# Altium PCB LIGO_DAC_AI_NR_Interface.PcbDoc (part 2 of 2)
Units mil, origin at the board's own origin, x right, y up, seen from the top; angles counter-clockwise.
Board outline 2600 x 10000 mil, 4 copper layers (Top Layer, Mid-Layer 1, Mid-Layer 2, Bottom Layer), stack 61.8 mil thick; 21 components, 77 nets, 221 pads, 42 vias.
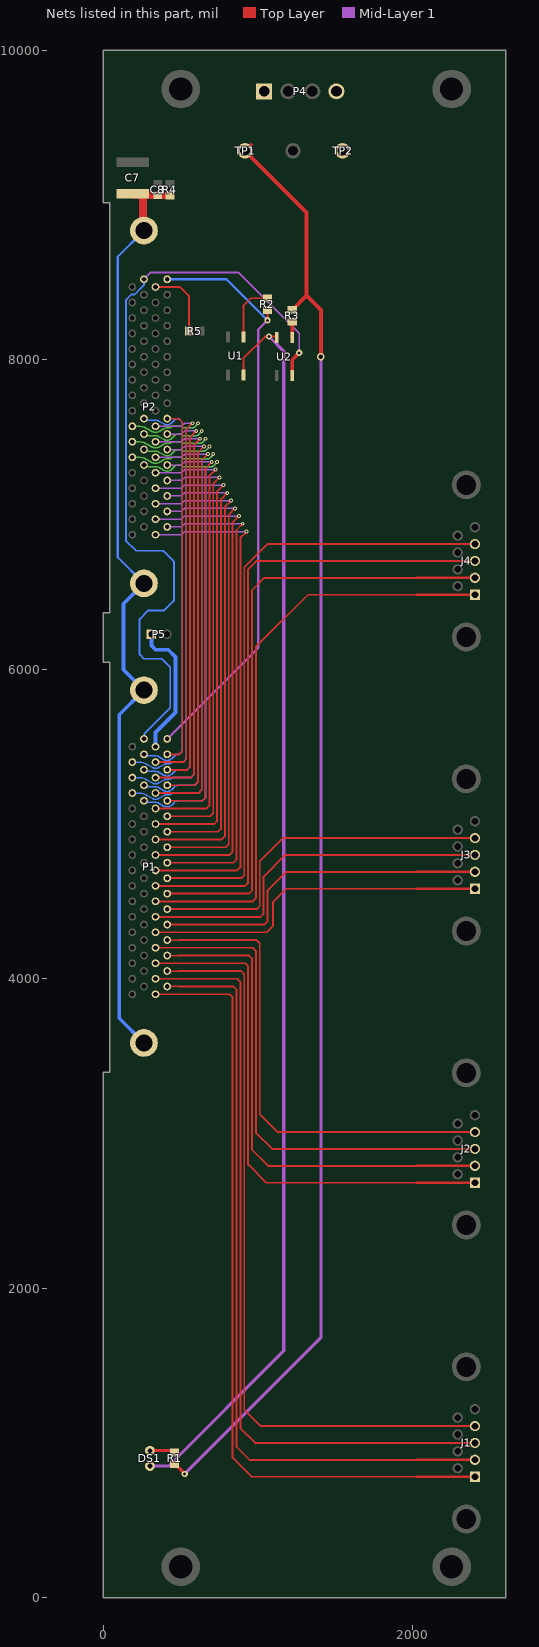
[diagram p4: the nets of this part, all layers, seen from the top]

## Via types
v1: diameter 25, hole 12, Top Layer to Bottom Layer, 30 vias
v2: diameter 40, hole 20, Top Layer to Bottom Layer, 11 vias
v3: diameter 50, hole 28, Top Layer to Bottom Layer, 1 vias

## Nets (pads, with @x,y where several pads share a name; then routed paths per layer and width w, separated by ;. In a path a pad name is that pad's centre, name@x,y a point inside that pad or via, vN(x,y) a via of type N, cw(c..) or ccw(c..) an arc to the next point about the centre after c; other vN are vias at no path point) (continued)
InputN26: P1.60 P2.44 | length 3166.4
  Mid-Layer 2 w8: v1@735,7337.52 v1(735,7340)
  Mid-Layer 2 w9: P2.44@261.81,7320 ccw(c285.95,7344.14) 285.95,7310 336.81,7310 cw(c336.81,7270) 358.01,7303.92 390.61,7286.08 ccw(c411.81,7320) 411.81,7280 ccw(c411.81,7320) 440.1,7291.72 440.1,7291.92 456.46,7308.28 cw(c484.74,7280) 484.74,7320 486.81,7320 505,7320
  Mid-Layer 2 w10: 505,7320 515,7310 702.28,7310 ccw(c702.28,7320) 707.64,7311.55 710.28,7313.23 716.74,7318.19 ccw(c700,7340) 723.39,7325.54 cw(c731.89,7320.27) 724.79,7327.31 733.25,7335.77 ccw(c729.02,7340) v1(735,7340)
  Bottom Layer w8: v1@735,7337.52 v1(735,7340)
  Bottom Layer w9: P1.60@261.81,5150 ccw(c285.95,5174.14) 285.95,5140 336.81,5140 cw(c336.81,5100) 358.01,5133.92 390.61,5116.08 ccw(c411.81,5150) 411.81,5110 ccw(c411.81,5150) 440.1,5121.72 440.1,5121.92 456.46,5138.28 cw(c484.74,5110) 484.74,5150
  Bottom Layer w10: 670,7310 702.28,7310 ccw(c702.28,7320) 707.64,7311.55 710.28,7313.23 716.74,7318.19 ccw(c700,7340) 723.39,7325.54 cw(c731.89,7320.27) 724.79,7327.31 733.25,7335.77 ccw(c729.02,7340) v1(735,7340)
  Bottom Layer w12: 484.74,5150 640,5150 660,5170 660,7296.81 ; 660,7300 670,7310
InputN27: P1.61 P2.45 | length 3257.4
  Mid-Layer 2 w8: v1@710,7387.52 v1(710,7390)
  Mid-Layer 2 w9: P2.45@186.81,7370 224.74,7370 226.94,7370 cw(c226.94,7264.19) 283.01,7353.92 283.21,7353.81 315.61,7336.08 ccw(c336.81,7370) 336.81,7330 ccw(c336.81,7370) 358.01,7336.08 390.61,7353.92 cw(c411.81,7320) 411.81,7360 424.74,7360 ccw(c424.74,7377.07) 436.81,7365 cw(c448.88,7352.93) 448.88,7370 486.81,7370 505,7370
  Mid-Layer 2 w10: 505,7370 515,7360 677.28,7360 ccw(c677.28,7370) 682.64,7361.55 685.28,7363.23 691.74,7368.19 ccw(c675,7390) 698.39,7375.54 cw(c706.89,7370.27) 699.79,7377.31 708.25,7385.77 ccw(c704.02,7390) v1(710,7390)
  Bottom Layer w8: v1@710,7387.52 v1(710,7390)
  Bottom Layer w9: P1.61@186.81,5200 224.74,5200 226.94,5200 cw(c226.94,5094.19) 283.01,5183.92 283.21,5183.81 315.61,5166.08 ccw(c336.81,5200) 336.81,5160 ccw(c336.81,5200) 358.01,5166.08 390.61,5183.92 cw(c411.81,5150) 411.81,5190 424.74,5190 ccw(c424.74,5207.07) 436.81,5195 cw(c448.88,5182.93) 448.88,5200
  Bottom Layer w10: 645,7360 677.28,7360 ccw(c677.28,7370) 682.64,7361.55 685.28,7363.23 691.74,7368.19 ccw(c675,7390) 698.39,7375.54 cw(c706.89,7370.27) 699.79,7377.31 708.25,7385.77 ccw(c704.02,7390) v1(710,7390)
  Bottom Layer w12: 448.88,5200 615,5200 635,5220 635,7346.81 ; 635,7350 645,7360
InputN28: P1.62 P2.46 | length 3066.4
  Mid-Layer 2 w8: v1@685,7437.52 v1(685,7440)
  Mid-Layer 2 w9: P2.46@261.81,7420 ccw(c285.95,7444.14) 285.95,7410 336.81,7410 cw(c336.81,7370) 358.01,7403.92 390.61,7386.08 ccw(c411.81,7420) 411.81,7380 ccw(c411.81,7420) 440.1,7391.72 440.1,7391.92 456.46,7408.28 cw(c484.74,7380) 484.74,7420 486.81,7420 505,7420
  Mid-Layer 2 w10: 505,7420 515,7410 652.28,7410 ccw(c652.28,7420) 657.64,7411.55 660.28,7413.23 666.74,7418.19 ccw(c650,7440) 673.39,7425.54 cw(c681.89,7420.27) 674.79,7427.31 683.25,7435.77 ccw(c679.02,7440) v1(685,7440)
  Bottom Layer w8: v1@685,7437.52 v1(685,7440)
  Bottom Layer w9: P1.62@261.81,5250 ccw(c285.95,5274.14) 285.95,5240 336.81,5240 cw(c336.81,5200) 358.01,5233.92 390.61,5216.08 ccw(c411.81,5250) 411.81,5210 ccw(c411.81,5250) 440.1,5221.72 440.1,5221.92 456.46,5238.28 cw(c484.74,5210) 484.74,5250
  Bottom Layer w10: 620,7410 652.28,7410 ccw(c652.28,7420) 657.64,7411.55 660.28,7413.23 666.74,7418.19 ccw(c650,7440) 673.39,7425.54 cw(c681.89,7420.27) 674.79,7427.31 683.25,7435.77 ccw(c679.02,7440) v1(685,7440)
  Bottom Layer w12: 484.74,5250 590,5250 610,5270 610,7396.81 ; 610,7400 620,7410
InputN29: P1.63 P2.47 | length 3157.4
  Mid-Layer 2 w8: v1@660,7487.52 v1(660,7490)
  Mid-Layer 2 w9: P2.47@186.81,7470 224.74,7470 226.94,7470 cw(c226.94,7364.19) 283.01,7453.92 283.21,7453.81 315.61,7436.08 ccw(c336.81,7470) 336.81,7430 ccw(c336.81,7470) 358.01,7436.08 390.61,7453.92 cw(c411.81,7420) 411.81,7460 424.74,7460 ccw(c424.74,7477.07) 436.81,7465 cw(c448.88,7452.93) 448.88,7470 486.81,7470 505,7470
  Mid-Layer 2 w10: 505,7470 515,7460 627.28,7460 ccw(c627.28,7470) 632.64,7461.55 635.28,7463.23 641.74,7468.19 ccw(c625,7490) 648.39,7475.54 cw(c656.89,7470.27) 649.79,7477.31 658.25,7485.77 ccw(c654.02,7490) v1(660,7490)
  Bottom Layer w8: v1@660,7487.52 v1(660,7490)
  Bottom Layer w9: P1.63@186.81,5300 224.74,5300 226.94,5300 cw(c226.94,5194.19) 283.01,5283.92 283.21,5283.81 315.61,5266.08 ccw(c336.81,5300) 336.81,5260 ccw(c336.81,5300) 358.01,5266.08 390.61,5283.92 cw(c411.81,5250) 411.81,5290 424.74,5290 ccw(c424.74,5307.07) 436.81,5295 cw(c448.88,5282.93) 448.88,5300
  Bottom Layer w10: 595,7460 627.28,7460 ccw(c627.28,7470) 632.64,7461.55 635.28,7463.23 641.74,7468.19 ccw(c625,7490) 648.39,7475.54 cw(c656.89,7470.27) 649.79,7477.31 658.25,7485.77 ccw(c654.02,7490) v1(660,7490)
  Bottom Layer w12: 448.88,5300 565,5300 585,5320 585,7446.81 ; 585,7450 595,7460
InputN30: P1.64 P2.48 | length 2969.6
  Mid-Layer 2 w8: v1@635,7537.52 v1(635,7540)
  Mid-Layer 2 w9: P2.48@261.81,7520 ccw(c285.95,7544.14) 285.95,7510 336.81,7510 cw(c336.81,7470) 358.01,7503.92 390.61,7486.08 ccw(c411.81,7520) 411.81,7480 ccw(c411.81,7520) 440.1,7491.72 440.1,7491.92 456.46,7508.28 cw(c484.74,7480) 484.74,7520 486.81,7520 505,7520
  Mid-Layer 2 w10: 505,7520 515,7510 602.28,7510 ccw(c602.28,7520) 607.64,7511.55 610.28,7513.23 616.74,7518.19 ccw(c600,7540) 623.39,7525.54 cw(c631.89,7520.27) 624.79,7527.31 633.25,7535.77 ccw(c629.02,7540) v1(635,7540)
  Bottom Layer w8: v1@635,7537.52 v1(635,7540)
  Bottom Layer w9: P1.64@261.81,5350 ccw(c285.95,5374.14) 285.95,5340 336.81,5340 cw(c336.81,5300) 358.01,5333.92 390.61,5316.08 ccw(c411.81,5350) 411.81,5310 ccw(c411.81,5350) 440.1,5321.72 440.1,5321.92 456.46,5338.28 cw(c484.74,5310) 484.74,5350
  Bottom Layer w10: 570,7510 602.28,7510 ccw(c602.28,7520) 607.64,7511.55 610.28,7513.23 616.74,7518.19 ccw(c600,7540) 623.39,7525.54 cw(c631.89,7520.27) 624.79,7527.31 633.25,7535.77 ccw(c629.02,7540) v1(635,7540)
  Bottom Layer w12: 484.74,5350 540,5350 560,5370 560,7500 570,7510
InputN31: P1.65 P2.49 | length 3083.2
  Mid-Layer 2 w8: v1@610,7587.52 v1(610,7590)
  Mid-Layer 2 w9: P2.49@186.81,7570 224.74,7570 226.94,7570 cw(c226.94,7464.19) 283.01,7553.92 283.21,7553.81 315.61,7536.08 ccw(c336.81,7570) 336.81,7530 ccw(c336.81,7570) 358.01,7536.08 390.61,7553.92 cw(c411.81,7520) 411.81,7560 424.74,7560 ccw(c424.74,7577.07) 436.81,7565 cw(c448.88,7552.93) 448.88,7570 486.81,7570 505,7570
  Mid-Layer 2 w10: 505,7570 515,7560 577.28,7560 ; 577.28,7560 ccw(c577.28,7570) 582.64,7561.55 ; 577.28,7560 ccw(c577.28,7570) 582.64,7561.55 ; 582.64,7561.55 585.28,7563.23 591.74,7568.19 ; 591.74,7568.19 ccw(c575,7590) 598.39,7575.54 ; 591.74,7568.19 ccw(c575,7590) 598.39,7575.54 ; 598.39,7575.54 cw(c606.89,7570.27) 599.79,7577.31 ; 598.39,7575.54 cw(c606.89,7570.27) 599.79,7577.31 ; 599.79,7577.31 v1@608.25,7585.77 ; v1@608.25,7585.77 ccw(c604.02,7590) v1(610,7590) cw(c604.02,7590) v1@608.25,7585.77
  Bottom Layer w8: v1@610,7587.52 v1(610,7590)
  Bottom Layer w9: P1.65@186.81,5400 224.74,5400 226.94,5400 cw(c226.94,5294.19) 283.01,5383.92 283.21,5383.81 315.61,5366.08 ccw(c336.81,5400) 336.81,5360 ccw(c336.81,5400) 358.01,5366.08 390.61,5383.92 cw(c411.81,5350) 411.81,5390 424.74,5390 ccw(c424.74,5407.07) 436.81,5395 cw(c448.88,5382.93) 448.88,5400
  Bottom Layer w10: 545,7560 577.28,7560 ccw(c577.28,7570) 582.64,7561.55 585.28,7563.23 591.74,7568.19 ccw(c575,7590) 598.39,7575.54 cw(c606.89,7570.27) 599.79,7577.31 608.25,7585.77 ccw(c604.02,7590) v1(610,7590)
  Bottom Layer w12: 448.88,5400 515,5400 535,5420 535,7550 545,7560
InputN32: P1.66 P2.50 | length 2682.6
  Bottom Layer w9: P1.66@261.81,5450 ccw(c285.95,5474.14) 285.95,5440 336.81,5440 cw(c336.81,5400) 358.01,5433.92 390.61,5416.08 ccw(c411.81,5450) 411.81,5410 ccw(c411.81,5450) 440.1,5421.72 440.1,5421.92 456.46,5438.28 cw(c484.74,5410) 484.74,5450 486.81,5450 ; P2.50@261.81,7620 ccw(c285.95,7644.14) 285.95,7610 336.81,7610 cw(c336.81,7570) 358.01,7603.92 390.61,7586.08 ccw(c411.81,7620) 411.81,7580 ccw(c411.81,7620) 440.1,7591.72 440.1,7591.92 456.46,7608.28 cw(c484.74,7580) 484.74,7620 486.81,7620
  Bottom Layer w12: 486.81,7620 509,7597.81 509,5469 490,5450
InputP1: J1.1 P1.1 | length 5098.4
  Top Layer w9: P1.1@336.81,3900 486.81,3900
  Top Layer w12: 486.81,3900 815,3900 835,3880 835,905 958.11,781.89 2025,781.89
  Top Layer w15: 2025,781.89 2075,781.89 J1.1@2400.91,781.89
InputP2: J1.2 P1.2 | length 4987.2
  Top Layer w9: P1.2@411.81,3950 486.81,3950
  Top Layer w12: 486.81,3950 840,3950 860,3930 860,975 944.05,890.95 2025,890.95
  Top Layer w15: 2025,890.95 2075,890.94 J1.2@2400.91,890.94
InputP3: J1.3 P1.3 | length 4996.7
  Top Layer w9: P1.3@336.81,4000 486.81,4000
  Top Layer w12: 486.81,4000 865,4000 885,3980 885,1095 980,1000 2025,1000
  Top Layer w15: 2025,1000 2075,1000 J1.3@2400.91,1000
InputP4: J1.4 P1.4 | length 4856.3
  Top Layer w9: P1.4@411.81,4050 486.81,4050
  Top Layer w12: 486.81,4050 890,4050 910,4030 910,1215 1015.94,1109.05 2018.11,1109.05
  Top Layer w15: 2018.11,1109.05 2075,1109.06 J1.4@2400.91,1109.06
InputP5: J2.1 P1.5 | length 3401.3
  Top Layer w9: P1.5@336.81,4100 486.81,4100
  Top Layer w12: 486.81,4100 915,4100 935,4080 935,2800 1053.11,2681.89 2025,2681.89
  Top Layer w15: 2025,2681.89 2075,2681.89 J2.1@2400.91,2681.89
InputP6: J2.2 P1.6 | length 3275.5
  Top Layer w9: P1.6@411.81,4150 486.81,4150
  Top Layer w12: 486.81,4150 940,4150 960,4130 960,2895 1064.05,2790.95 2025,2790.95
  Top Layer w15: 2025,2790.95 2075,2790.94 J2.2@2400.91,2790.94
InputP7: J2.3 P1.7 | length 3290.9
  Top Layer w9: P1.7@336.81,4200 486.81,4200
  Top Layer w12: 486.81,4200 965,4200 985,4180 985,3005 1090,2900 2025,2900
  Top Layer w15: 2025,2900 2075,2900 J2.3@2400.91,2900
InputP8: J2.4 P1.8 | length 3150.4
  Top Layer w9: P1.8@411.81,4250 486.81,4250
  Top Layer w12: 486.81,4250 990,4250 1010,4230 1010,3125 1125.94,3009.06 2018.11,3009.05
  Top Layer w15: 2018.11,3009.05 2075,3009.06 J2.4@2400.91,3009.06
InputP9: J3.1 P1.9 | length 2271.7
  Top Layer w12: P1.9@336.81,4300 1055,4300 1095,4340 1095,4495 1181.89,4581.89 2025,4581.89
  Top Layer w15: 2025,4581.89 2075,4581.89 J3.1@2400.91,4581.89
InputP10: J3.2 P1.10 | length 2247.5
  Top Layer w12: P1.10@411.81,4350 1040,4350 1060,4370 1060,4570 1180.95,4690.95 2025,4690.95
  Top Layer w15: 2025,4690.95 2075,4690.94 J3.2@2400.91,4690.94
InputP11: J3.3 P1.11 | length 2370.4
  Top Layer w12: P1.11@336.81,4400 1015,4400 1035,4420 1035,4660 1175,4800 2025,4800
  Top Layer w15: 2025,4800 2075,4800 J3.3@2400.91,4800
InputP12: J3.4 P1.12 | length 2349.1
  Top Layer w12: P1.12@411.81,4450 990,4450 1010,4470 1010,4760 1159.05,4909.05 2018.11,4909.06
  Top Layer w15: 2018.11,4909.06 2075,4909.06 J3.4@2400.91,4909.06
InputP13: J4.1 P1.13 | length 3836.9
  Top Layer w12: P1.13@336.81,4500 965,4500 985,4520 985,6145 1321.89,6481.89 2025,6481.89
  Top Layer w15: 2025,6481.89 2075,6481.89 J4.1@2400.91,6481.89
InputP14: J4.2 P1.14 | length 3970.9
  Top Layer w12: P1.14@411.81,4550 940,4550 960,4570 960,6510 1040,6590 2024.05,6590 2025,6590.95
  Top Layer w15: 2025,6590.95 2075,6590.94 J4.2@2400.91,6590.94
InputP15: J4.3 P1.15 | length 4120.2
  Top Layer w12: P1.15@336.81,4600 915,4600 935,4620 935,6645 990,6700 2025,6700
  Top Layer w15: 2025,6700 2075,6700 J4.3@2400.91,6700
InputP16: J4.4 P1.16 | length 4049.1
  Top Layer w12: P1.16@411.81,4650 890,4650 910,4670 910,6660 1059.05,6809.06 2018.11,6809.06
  Top Layer w15: 2018.11,6809.06 2075,6809.06 J4.4@2400.91,6809.06
InputP17: P1.17 P2.1 | length 3336.3
  Top Layer w12: P1.17@336.81,4700 865,4700 885,4720 885,6846.81 ; 885,6850 v1(925,6890)
  Mid-Layer 1 w9: P2.1@336.81,6870 486.81,6870 505,6870
  Mid-Layer 1 w10: 505,6870 525,6890 v1(925,6890)
InputP18: P1.18 P2.2 | length 3136.3
  Top Layer w12: P1.18@411.81,4750 840,4750 860,4770 860,6896.81 ; 860,6900 v1(900,6940)
  Mid-Layer 1 w9: P2.2@411.81,6920 486.81,6920 505,6920
  Mid-Layer 1 w10: 505,6920 525,6940 v1(900,6940)
InputP19: P1.19 P2.3 | length 3236.3
  Top Layer w12: P1.19@336.81,4800 815,4800 835,4820 835,6946.81 ; 835,6950 v1(875,6990)
  Mid-Layer 1 w9: P2.3@336.81,6970 486.81,6970 505,6970
  Mid-Layer 1 w10: 505,6970 525,6990 v1(875,6990)
InputP20: P1.20 P2.4 | length 3036.3
  Top Layer w12: P1.20@411.81,4850 790,4850 810,4870 810,6996.81 ; 810,7000 v1(850,7040)
  Mid-Layer 1 w9: P2.4@411.81,7020 486.81,7020 505,7020
  Mid-Layer 1 w10: 505,7020 525,7040 v1(850,7040)
InputP21: P1.21 P2.5 | length 3136.3
  Top Layer w12: P1.21@336.81,4900 765,4900 785,4920 785,7046.81 ; 785,7050 v1(825,7090)
  Mid-Layer 1 w9: P2.5@336.81,7070 486.81,7070 505,7070
  Mid-Layer 1 w10: 505,7070 525,7090 v1(825,7090)
InputP22: P1.22 P2.6 | length 2936.3
  Top Layer w12: P1.22@411.81,4950 740,4950 760,4970 760,7096.81 ; 760,7100 v1(800,7140)
  Mid-Layer 1 w9: P2.6@411.81,7120 486.81,7120 505,7120
  Mid-Layer 1 w10: 505,7120 525,7140 v1(800,7140)
InputP23: P1.23 P2.7 | length 3036.3
  Top Layer w12: P1.23@336.81,5000 715,5000 735,5020 735,7146.81 ; 735,7150 v1(775,7190)
  Mid-Layer 1 w9: P2.7@336.81,7170 486.81,7170 505,7170
  Mid-Layer 1 w10: 505,7170 525,7190 v1(775,7190)
InputP24: P1.24 P2.8 | length 2836.3
  Top Layer w12: P1.24@411.81,5050 690,5050 710,5070 710,7196.81 ; 710,7200 v1(750,7240)
  Mid-Layer 1 w9: P2.8@411.81,7220 486.81,7220 505,7220
  Mid-Layer 1 w10: 505,7220 525,7240 v1(750,7240)
InputP25: P1.25 P2.9 | length 2936.3
  Top Layer w12: P1.25@336.81,5100 665,5100 685,5120 685,7246.81 ; 685,7250 v1(725,7290)
  Mid-Layer 1 w9: P2.9@336.81,7270 486.81,7270 505,7270
  Mid-Layer 1 w10: 505,7270 525,7290 v1(725,7290)
InputP26: P1.26 P2.10 | length 2736.3
  Top Layer w12: P1.26@411.81,5150 640,5150 660,5170 660,7296.81 ; 660,7300 v1(700,7340)
  Mid-Layer 1 w9: P2.10@411.81,7320 486.81,7320 505,7320
  Mid-Layer 1 w10: 505,7320 525,7340 v1(700,7340)
InputP27: P1.27 P2.11 | length 2836.3
  Top Layer w12: P1.27@336.81,5200 615,5200 635,5220 635,7346.81 ; 635,7350 v1(675,7390)
  Mid-Layer 1 w9: P2.11@336.81,7370 486.81,7370 505,7370
  Mid-Layer 1 w10: 505,7370 525,7390 v1(675,7390)
InputP28: P1.28 P2.12 | length 2636.3
  Top Layer w12: P1.28@411.81,5250 590,5250 610,5270 610,7396.81 ; 610,7400 v1(650,7440)
  Mid-Layer 1 w9: P2.12@411.81,7420 486.81,7420 505,7420
  Mid-Layer 1 w10: 505,7420 525,7440 v1(650,7440)
InputP29: P1.29 P2.13 | length 2736.3
  Top Layer w12: P1.29@336.81,5300 565,5300 585,5320 585,7446.81 ; 585,7450 v1(625,7490)
  Mid-Layer 1 w9: P2.13@336.81,7470 486.81,7470 505,7470
  Mid-Layer 1 w10: 505,7470 525,7490 v1(625,7490)
InputP30: P1.30 P2.14 | length 2539.5
  Top Layer w12: P1.30@411.81,5350 540,5350 560,5370 560,7500 v1(600,7540)
  Mid-Layer 1 w9: P2.14@411.81,7520 486.81,7520 505,7520
  Mid-Layer 1 w10: 505,7520 525,7540 v1(600,7540)
InputP31: P1.31 P2.15 | length 2639.5
  Top Layer w12: P1.31@336.81,5400 515,5400 535,5420 535,7550 v1(575,7590)
  Mid-Layer 1 w9: P2.15@336.81,7570 486.81,7570 505,7570
  Mid-Layer 1 w10: 505,7570 525,7590 v1(575,7590)
InputP32: P1.32 P2.16 | length 2340.3
  Top Layer w9: P2.16@411.81,7620 486.81,7620
  Top Layer w12: P1.32@411.81,5450 490,5450 509,5469 509,7597.81 486.81,7620
InputRTN: P1.33 P5.1 | length 891.8
  Bottom Layer w25: P5.1@310,6226.5 310,6153 337,6126 419,6126 465,6080 465,5720 336.81,5591.81 P1.33@336.81,5500
NetDS1_1: DS1.1 U1.4 U2.2 | length 8152.5
  Top Layer w12: U1.4@905,7901.97 905,8010 1045,8150 1114.19,8150 1120,8144.19 U2.2@1120,8143.03
  Mid-Layer 1 w20: DS1.1@300,850 420,850 1165,1595 1165,8055 v2(1070,8150)
NetDS1_2: DS1.2 R1.1 | length 154.9
  Top Layer w20: DS1.2@300,950 R1.1@454.88,950
NetP2_33: P2.33 R5.1 | length 467
  Top Layer w12: P2.33@336.81,8469.81 495.19,8469.81 552.6,8412.4 R5.1@552.6,8185
NetR2_2: R2.2 U1.1 | length 376.6
  Top Layer w12: U1.1@905,8148.03 905,8350 952.4,8397.4 R2.2@1060,8397.4
NetR3_1: R3.1 U2.1 | length 104.6
  Top Layer w25: U2.1@1220,8143.03 R3.1@1220,8247.6
SH: C7.2 C8.2 P1.69 P1.70 P2.69 P2.70 R4.1 | length 6080.7
  Top Layer w25: P2.70@255,8841.77 P2.70@261.81,8834.96
  Top Layer w50: C7.2@196.5,9066.14 295.08,9066.14 298.62,9062.6 R4.1@425,9062.6 ; P2.70@255,8841.77 C7.2@255,9051.54
  Bottom Layer w15: P2.69@261.81,6555.04 92.5,6724.35 92.5,8665.65 P2.70@261.81,8834.96
  Bottom Layer w25: P1.69@261.81,3585.04 102.5,3744.35 102.5,5705.65 P1.70@261.81,5864.96 130,5996.77 130,6423.23 P2.69@261.81,6555.04
VIN+: P4.1 R1.2 R3.2 TP1.1 | length 9396.8
  Top Layer w20: R1.2@460,862.6 463.94,862.6 479.53,847.01 479.53,845.47 v2(525,800) ; TP1.1@915,9350 955,9390
  Top Layer w25: TP1.1@915,9350 1312.6,8952.4 1312.6,8415 ; R3.2@1220,8322.4 1312.6,8415 ; v3(1405,8020) 1405,8322.6 1312.6,8415
  Mid-Layer 1 w20: v2(525,800) 1405,1680 v3(1405,8020)
Vin-: P4.4 TP2.1
WD: P1.34 P2.34 R2.1 | length 3799
  Top Layer w12: v2(1060,8255) R2.1@1060,8322.6
  Mid-Layer 1 w15: P1.34@411.81,5550 1000,6138.19 1000,8195 v2(1060,8255)
  Bottom Layer w15: P2.34@411.81,8520 795,8520 v2(1060,8255)
WDM: P1.68 P2.68 U2.4 | length 5110.1
  Top Layer w25: U2.4@1220,7896.97 1220,8000 v2(1265,8045)
  Mid-Layer 1 w12: P2.68@261.81,8520 306.81,8565 870,8565 1265,8170 v2(1265,8045)
  Bottom Layer w12: P1.68@261.81,5550 264.31,5552.5 264.31,5584.31 432,5752 432,6013 377,6068 262,6068 234,6096 234,6324 290,6380 393,6380 455,6442 455,6697 386,6766 210.77,6766 145,6831.77 145,8386.17 180.83,8422 201,8422 261.81,8482.81 P2.68@261.81,8520
pads on no net: J1.5 J1.10 J1.11 J2.5 J2.10 J2.11 J3.5 J3.10 J3.11 J4.5 J4.10 J4.11 P2.17 P2.18 P2.19 P2.20 P2.21 P2.22 P2.23 P2.24 P2.25 P2.26 P2.27 P2.28 P2.29 P2.30 P2.31 P2.32 P2.51 P2.52 P2.53 P2.54 P2.55 P2.56 P2.57 P2.58 P2.59 P2.60 P2.61 P2.62 P2.63 P2.64 P2.65 P2.66

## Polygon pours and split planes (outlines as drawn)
GND on Mid-Layer 2 "GND_L03_P000" (solid, pour order 0): 50,9950 2550,9950 2550,50 50,50 50,3350 100,3350 100,9050 50,9050

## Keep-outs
Keep-Out Layer:
  lines w10: 50,50 50,3350 70,3350 70,6075 70,6325 70,9050 50,9050 50,9950 2550,9950 2550,50 50,50
  lines w20: 0,0 0,10000 2600,10000 2600,0 0,0

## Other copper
Top Layer:
  rectangle net GND: 85,9245 365,9420
  rectangle net GND: 325,9115 548.73,9420
  rectangle net VIN+: 835,9185 1103.22,9790
  rectangle net Vin-: 1455,9300 1655,9790
  rectangle net Vin-: 1455,9180 1655,9410
Mid-Layer 2:
  pour cut-out: 150,7650 150,6800 1050,6800 1050,7650

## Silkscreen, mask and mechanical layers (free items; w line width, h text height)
Top Overlay:
  region: 825,1845 825,3140 465.19,3140 465.19,1845
  lines w20: 470.5,6226.5 510.5,6226.5 618,6334 763,6334
  text "CH 13-16" at 2050,6575 h100 r90
  text "DAC RTN to GND Connection" at 668,6369 h75 r90
  text "Jumper Nominally Installed" at 753,6369 h75 r90
  text "CH 9-12" at 2050,4750 h100 r90
  text "CH 5-8" at 2050,2925 h100 r90
  text "S/N" at 820,1715 h75 r90
  text "REV: 1" at 525,1620 h75 r90
  text "LIGO DAC AI Interface" at 287,1617 h150 r90
  text "D2500097" at 412,1617 h125 r90
  text "CH 1-4" at 2050,1050 h100 r90
Mechanical 1:
  the board outline again, w20
Drill Drawing:
  circle w10: c3071.67,93.12 r20
  circle w10: c3071.67,93.12 r33.33
  circle w10: c3671.67,93.12 r33.33
  lines w10: 3188.34,59.79 3205,59.79 3221.67,76.46 3238.33,59.79 3255,59.79 3255,76.46 3238.33,93.12 3255,109.79 3255,126.46 3238.33,126.46 3221.67,109.79 3205,126.46 3188.34,126.46 3188.34,109.79 3205,93.12 3188.34,76.46 3188.34,59.79 ; 3338.34,59.79 3355,93.12 3338.34,126.46 3371.67,109.79 3405,126.46 3388.33,93.12 3405,59.79 3371.67,76.46 3338.34,59.79 ; 3351.67,73.12 3361.67,93.12 3351.67,113.12 3371.67,103.12 3391.67,113.12 3381.67,93.12 3391.67,73.12 3371.67,83.12 3351.67,73.12 ; 3488.34,93.12 3521.67,126.46 3555,93.12 3521.67,59.79 3488.34,93.12 ; 3788.34,59.79 3805,93.12 3788.34,126.46 3821.67,109.79 3855,126.46 3838.33,93.12 3855,59.79 3821.67,76.46 3788.34,59.79 ; 3938.34,59.79 3938.34,126.46 4005,126.46 4005,59.79 3938.34,59.79 ; 3951.67,73.12 3951.67,113.12 3991.67,113.12 3991.67,73.12 3951.67,73.12 ; 4088.34,59.79 4088.34,126.46 4155,93.12 4088.34,59.79 ; 4101.67,73.12 4101.67,113.12 4141.67,93.12 4101.67,73.12 ; 4238.34,59.79 4238.34,126.46 4305,126.46 4305,59.79 4238.34,59.79 ; 4388.34,59.79 4388.34,126.46 4455,93.12 4388.34,59.79 ; 4538.34,93.12 4555,76.46 4555,59.79 4571.67,76.46 4588.33,59.79 4588.33,76.46 4605,93.12 4588.33,109.79 4588.33,126.46 4571.67,109.79 4555,126.46 4555,109.79 4538.34,93.12 ; 4551.67,93.12 4561.67,83.12 4561.67,73.12 4571.67,83.12 4581.67,73.12 4581.67,83.12 4591.67,93.12 4581.67,103.12 4581.67,113.12 4571.67,103.12 4561.67,113.12 4561.67,103.12 4551.67,93.12 ; 4688.34,93.12 4705,76.46 4705,59.79 4721.67,76.46 4738.33,59.79 4738.33,76.46 4755,93.12 4738.33,109.79 4738.33,126.46 4721.67,109.79 4705,126.46 4705,109.79 4688.34,93.12
  lines w15: 2850,550.87 4950,550.87 ; 2850,1140.72 4950,1140.72 ; 2850,2290.38 4950,2290.38 ; 2850,2796.26 4950,2796.26 ; 2850,3530.06 4950,3530.06 ; 2850,5029.61 4950,5029.61 ; 2850,5619.46 4950,5619.46 ; 2850,6365.26 4950,6365.26 ; 2850,7015.09 4950,7015.09 ; 2850,7868.85 4950,7868.85 ; 2850,9202.46 4950,9202.46 ; 3000,0 3000,10581.07 ; 4800,0 4800,10581.07 ; 2850,0 2850,10581.07 4950,10581.07 4950,0 2850,0
  text "Hole Tolerance (-)" at 2955,9247.46 h72 r90
  text "Hole Tolerance (+)" at 2955,7913.85 h72 r90
  text "Description" at 2955,7060.09 h72 r90
  text "Template" at 2955,6410.26 h72 r90
  text "v127h71" at 3105,6410.26 h60 r90
  text "c160h80" at 3255,6410.26 h60 r90
  text "(Mixed)" at 3405,6410.26 h60 r90
  text "c254h158" at 3555,6410.26 h60 r90
  text "(Mixed)" at 3705,6410.26 h60 r90
  text "c455h277" at 3855,6410.26 h60 r90
  text "c635h381" at 4005,6410.26 h60 r90
  text "c476h326" at 4155,6410.26 h60 r90
  text "v102h51" at 4305,6410.26 h60 r90
  text "v64h30" at 4455,6410.26 h60 r90
  text "(Mixed)" at 4605,6410.26 h60 r90
  text "c127h76" at 4755,6410.26 h60 r90
  text "Pad Shape" at 2955,5664.46 h72 r90
  text "Rounded" at 3105,5664.46 h60 r90
  text "Rounded" at 3255,5664.46 h60 r90
  text "(Mixed)" at 3405,5664.46 h60 r90
  text "Rounded" at 3555,5664.46 h60 r90
  text "(Mixed)" at 3705,5664.46 h60 r90
  text "Rounded" at 3855,5664.46 h60 r90
  text "Rounded" at 4005,5664.46 h60 r90
  text "Rounded" at 4155,5664.46 h60 r90
  text "Rounded" at 4305,5664.46 h60 r90
  text "Rounded" at 4455,5664.46 h60 r90
  text "(Mixed)" at 4605,5664.46 h60 r90
  text "Rounded" at 4755,5664.46 h60 r90
  text "Via/Pad" at 2955,5074.61 h72 r90
  text "Via" at 3105,5074.61 h60 r90
  text "Pad" at 3255,5074.61 h60 r90
  text "Pad" at 3405,5074.61 h60 r90
  text "Pad" at 3555,5074.61 h60 r90
  text "Pad" at 3705,5074.61 h60 r90
  text "Pad" at 3855,5074.61 h60 r90
  text "Pad" at 4005,5074.61 h60 r90
  text "Pad" at 4155,5074.61 h60 r90
  text "Via" at 4305,5074.61 h60 r90
  text "Via" at 4455,5074.61 h60 r90
  text "Pad" at 4605,5074.61 h60 r90
  text "Pad" at 4755,5074.61 h60 r90
  text "Drill Layer Pair" at 2955,3575.06 h72 r90
  text "Top Layer - Bottom Layer" at 3105,3575.06 h60 r90
  text "Top Layer - Bottom Layer" at 3255,3575.06 h60 r90
  text "Top Layer - Bottom Layer" at 3405,3575.06 h60 r90
  text "Top Layer - Bottom Layer" at 3555,3575.06 h60 r90
  text "Top Layer - Bottom Layer" at 3705,3575.06 h60 r90
  text "Top Layer - Bottom Layer" at 3855,3575.06 h60 r90
  text "Top Layer - Bottom Layer" at 4005,3575.06 h60 r90
  text "Top Layer - Bottom Layer" at 4155,3575.06 h60 r90
  text "Top Layer - Bottom Layer" at 4305,3575.06 h60 r90
  text "Top Layer - Bottom Layer" at 4455,3575.06 h60 r90
  text "Top Layer - Bottom Layer" at 4605,3575.06 h60 r90
  text "Top Layer - Bottom Layer" at 4755,3575.06 h60 r90
  text "Hole Type" at 2955,2841.26 h72 r90
  text "Round" at 3105,2841.26 h60 r90
  text "Round" at 3255,2841.26 h60 r90
  text "Round" at 3405,2841.26 h60 r90
  text "Round" at 3555,2841.26 h60 r90
  text "Round" at 3705,2841.26 h60 r90
  text "Round" at 3855,2841.26 h60 r90
  text "Round" at 4005,2841.26 h60 r90
  text "Round" at 4155,2841.26 h60 r90
  text "Round" at 4305,2841.26 h60 r90
  text "Round" at 4455,2841.26 h60 r90
  text "Round" at 4605,2841.26 h60 r90
  text "Round" at 4755,2841.26 h60 r90
  text "Plated" at 2955,2335.38 h72 r90
  text "PTH" at 3105,2335.38 h60 r90
  text "PTH" at 3255,2335.38 h60 r90
  text "PTH" at 3405,2335.38 h60 r90
  text "PTH" at 3555,2335.38 h60 r90
  text "PTH" at 3705,2335.38 h60 r90
  text "PTH" at 3855,2335.38 h60 r90
  text "PTH" at 4005,2335.38 h60 r90
  text "PTH" at 4155,2335.38 h60 r90
  text "PTH" at 4305,2335.38 h60 r90
  text "PTH" at 4455,2335.38 h60 r90
  text "PTH" at 4605,2335.38 h60 r90
  text "PTH" at 4755,2335.38 h60 r90
  text "Hole Size" at 2955,1185.72 h72 r90
  text "0.711mm (28.00mil)" at 3105,1185.72 h60 r90
  text "0.800mm (31.50mil)" at 3255,1185.72 h60 r90
  text "1.020mm (40.16mil)" at 3405,1185.72 h60 r90
  text "1.580mm (62.21mil)" at 3555,1185.72 h60 r90
  text "1.750mm (68.90mil)" at 3705,1185.72 h60 r90
  text "2.770mm (109.06mil)" at 3855,1185.72 h60 r90
  text "3.810mm (150.00mil)" at 4005,1185.72 h60 r90
  text "3.260mm (128.35mil)" at 4155,1185.72 h60 r90
  text "0.508mm (20.00mil)" at 4305,1185.72 h60 r90
  text "0.305mm (12.00mil)" at 4455,1185.72 h60 r90
  text "1.090mm (42.91mil)" at 4605,1185.72 h60 r90
  text "0.762mm (30.00mil)" at 4755,1185.72 h60 r90
  text "Count" at 2955,595.87 h72 r90
  text "1" at 3105,595.87 h60 r90
  text "2" at 3255,595.87 h60 r90
  text "2" at 3405,595.87 h60 r90
  text "3" at 3555,595.87 h60 r90
  text "4" at 3705,595.87 h60 r90
  text "4" at 3855,595.87 h60 r90
  text "4" at 4005,595.87 h60 r90
  text "8" at 4155,595.87 h60 r90
  text "11" at 4305,595.87 h60 r90
  text "30" at 4455,595.87 h60 r90
  text "36" at 4605,595.87 h60 r90
  text "136" at 4755,595.87 h60 r90
  text "241 Total" at 4905,595.87 h60 r90
  text "Symbol" at 2955,90 h72 r90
